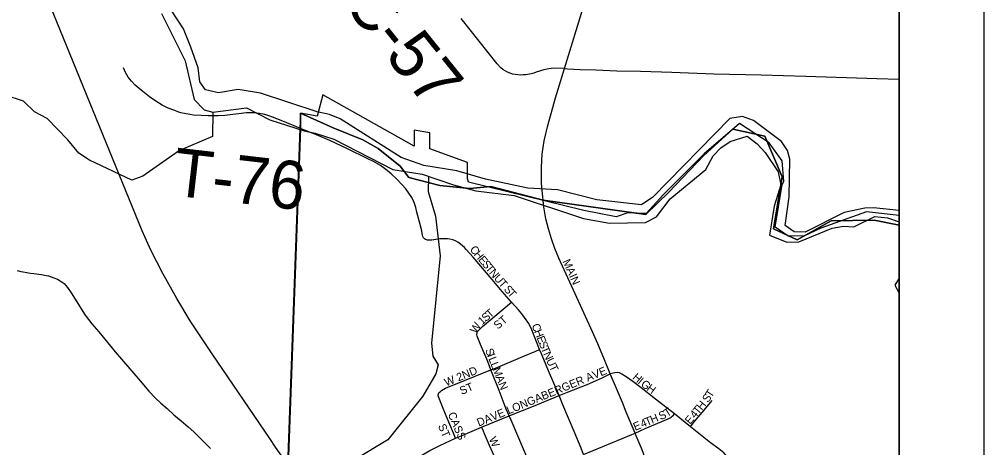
# Model space of a CAD drawing. Extents: x 0 to 34, y 0 to 22.
# Drawn here: x 29.776 to 30.917, y 15.366 to 15.873 of the extents above; entities that cross this region are included whole.
import ezdxf

# ---------------------------------------------------------------- set-up
doc = ezdxf.new("R2010")
doc.units = 0
for name, color, linetype in [('GM_X_Adjacent_County', 7, 'Continuous'), ('GM_X_City_Street', 7, 'Continuous'), ('GM_X_City_Street_Text', 7, 'Continuous'), ('GM_X_Corporation', 7, 'Continuous'), ('GM_X_County', 7, 'Continuous'), ('GM_X_County_Road', 7, 'Continuous'), ('GM_X_County_Road_Text', 7, 'Continuous'), ('GM_X_Minor_River', 7, 'Continuous'), ('GM_X_State_Route', 7, 'Continuous'), ('GM_X_Township', 7, 'Continuous'), ('GM_X_Township_Road', 7, 'Continuous'), ('GM_X_Township_Road_Text', 7, 'Continuous'), ('SH_Data', 7, 'Continuous')]:
    doc.layers.add(name, color=color, linetype=linetype)

msp = doc.modelspace()

# ---------------------------------------------------------------- linework, layer by layer
at = {"layer": 'GM_X_Adjacent_County'}
msp.add_lwpolyline([(24.0167, 18.0693), (24.0167, 14.1), (30.8167, 14.1), (30.8167, 17.8174)], dxfattribs=at)
at = {"layer": 'GM_X_City_Street'}
for points in [[(30.3579, 15.5381), (30.3471, 15.5507), (30.335, 15.5649), (30.3129, 15.5911), (30.3044, 15.6003), (30.3023, 15.6026), (30.3001, 15.6047), (30.2977, 15.6067), (30.2946, 15.6088), (30.2919, 15.6105), (30.2885, 15.6119), (30.2852, 15.6127), (30.2822, 15.6131), (30.2779, 15.6131), (30.2734, 15.6129), (30.2637, 15.6113), (30.2607, 15.6112), (30.2588, 15.6113), (30.2575, 15.6116), (30.2562, 15.6122), (30.2551, 15.6131), (30.2541, 15.6142), (30.2533, 15.6156), (30.2527, 15.6171), (30.2515, 15.624), (30.2462, 15.6445), (30.2447, 15.6501), (30.2428, 15.6559), (30.24, 15.6617), (30.2366, 15.667), (30.2332, 15.672), (30.2285, 15.6773), (30.2226, 15.6834), (30.2158, 15.6897), (30.2111, 15.6939), (30.2029, 15.6999), (30.195, 15.7045), (30.1881, 15.7077), (30.1641, 15.7196), (30.1431, 15.7293), (30.1301, 15.7347), (30.1084, 15.7436), (30.1038, 15.7455)], [(30.4749, 15.453), (30.4671, 15.4716), (30.46, 15.4888), (30.4539, 15.503), (30.4334, 15.548), (30.4141, 15.5901), (30.4095, 15.6015), (30.4053, 15.6131), (30.4018, 15.6249), (30.3988, 15.6368), (30.3971, 15.6459), (30.3963, 15.6508), (30.3959, 15.6542)], [(30.3172, 15.5003), (30.3173, 15.5016), (30.3175, 15.5023), (30.318, 15.5031), (30.3194, 15.5048), (30.3239, 15.509), (30.3579, 15.5381)], [(30.3912, 15.482), (30.3822, 15.5053), (30.3786, 15.5126), (30.3736, 15.5199), (30.3701, 15.5241), (30.3663, 15.529), (30.3579, 15.5381)], [(30.3338, 15.4578), (30.3299, 15.4678), (30.3212, 15.4878), (30.3181, 15.4956), (30.3174, 15.4979), (30.3172, 15.4992), (30.3172, 15.5003)], [(30.3338, 15.4578), (30.339, 15.4599), (30.3715, 15.4736), (30.3867, 15.48), (30.3912, 15.482)], [(30.4143, 15.4274), (30.402, 15.4566), (30.3936, 15.4767), (30.3912, 15.482)], [(30.2727, 15.4315), (30.274, 15.4324), (30.2752, 15.4333), (30.2801, 15.436), (30.3338, 15.4578)], [(30.3553, 15.4036), (30.3519, 15.4115), (30.3433, 15.4333), (30.3338, 15.4578)], [(30.4143, 15.4274), (30.4244, 15.4316), (30.4476, 15.4407), (30.4647, 15.4481), (30.4749, 15.453)], [(30.5509, 15.4059), (30.5283, 15.4233), (30.5113, 15.4366), (30.5015, 15.4442), (30.4939, 15.4495), (30.4887, 15.4528), (30.4858, 15.4543), (30.4832, 15.4548), (30.4802, 15.4544), (30.4749, 15.453)], [(30.5043, 15.3829), (30.5009, 15.3911), (30.4984, 15.3966), (30.4938, 15.4078), (30.4893, 15.4191), (30.4858, 15.4276), (30.4823, 15.4358), (30.4749, 15.453)], [(30.2919, 15.3768), (30.2893, 15.3829), (30.2808, 15.4036), (30.2755, 15.416), (30.2719, 15.4252), (30.2715, 15.4272), (30.2715, 15.4284), (30.2717, 15.4296), (30.2721, 15.4307), (30.2727, 15.4315)], [(30.3553, 15.4036), (30.3582, 15.4047), (30.3842, 15.415), (30.4143, 15.4274)], [(30.4433, 15.3578), (30.4404, 15.365), (30.4321, 15.3849), (30.4189, 15.4165), (30.4143, 15.4274)], [(30.5698, 15.3906), (30.5743, 15.3962), (30.5858, 15.41), (30.5935, 15.4191), (30.5954, 15.4214)], [(30.3227, 15.39), (30.3466, 15.4), (30.3553, 15.4036)], [(30.3856, 15.3339), (30.3835, 15.3384), (30.3736, 15.3612), (30.3576, 15.3983), (30.3553, 15.4036)], [(30.5043, 15.3829), (30.5162, 15.3883), (30.5435, 15.3998), (30.5457, 15.4011), (30.547, 15.402), (30.5482, 15.403), (30.5495, 15.4041), (30.5509, 15.4059)], [(30.5698, 15.3906), (30.5509, 15.4059)], [(30.6182, 15.3491), (30.6142, 15.3542), (30.6121, 15.3564), (30.6091, 15.3595), (30.6033, 15.3642), (30.5936, 15.3716), (30.5698, 15.3906)], [(30.2919, 15.3768), (30.3033, 15.3818), (30.3227, 15.39)], [(30.3227, 15.39), (30.3245, 15.3856), (30.3256, 15.3827), (30.3281, 15.3771), (30.3318, 15.3686), (30.3373, 15.3564), (30.3471, 15.3316), (30.3484, 15.3288), (30.3495, 15.3271), (30.3505, 15.3261), (30.3512, 15.3253), (30.3522, 15.3247), (30.3535, 15.324), (30.3541, 15.3238), (30.3549, 15.3236), (30.3562, 15.3235), (30.3578, 15.3236), (30.3598, 15.3238), (30.363, 15.3245), (30.3659, 15.3257), (30.3821, 15.3324)], [(30.4433, 15.3578), (30.5004, 15.3813), (30.5043, 15.3829)], [(30.533, 15.314), (30.5282, 15.3252), (30.5225, 15.3387), (30.5204, 15.3437), (30.5159, 15.3547), (30.5125, 15.363), (30.5102, 15.3687), (30.509, 15.3715), (30.5056, 15.3799), (30.5043, 15.3829)], [(30.177, 15.3087), (30.1998, 15.3237), (30.2321, 15.3442), (30.2474, 15.3541), (30.2616, 15.3623), (30.2733, 15.3683), (30.2919, 15.3768)]]:
    msp.add_lwpolyline(points, dxfattribs=at)
at = {"layer": 'GM_X_Corporation'}
msp.add_line((30.8167, 14.6286), (30.8167, 15.6406), dxfattribs=at)
msp.add_lwpolyline([(30.8167, 15.6406), (30.778, 15.6449), (30.7239, 15.6257), (30.7046, 15.6166), (30.6855, 15.6161), (30.6699, 15.6269), (30.6783, 15.6773), (30.6801, 15.681), (30.6781, 15.7053), (30.6627, 15.7266), (30.6278, 15.7494), (30.5858, 15.7134), (30.5377, 15.6653), (30.5175, 15.6428), (30.4957, 15.6437), (30.4819, 15.6389), (30.4435, 15.6466), (30.3072, 15.6799), (30.3059, 15.6843), (30.3059, 15.7033), (30.2614, 15.7195), (30.2614, 15.7384), (30.2428, 15.7417), (30.2428, 15.7227), (30.1349, 15.7832), (30.128, 15.758), (30.1084, 15.7615), (30.1076, 15.7433), (30.0929, 15.3447)], dxfattribs=at)
at = {"layer": 'GM_X_County'}
msp.add_lwpolyline([(24.0167, 18.0693), (24.0167, 14.1), (30.8167, 14.1), (30.8167, 17.8174)], dxfattribs=at)
at = {"layer": 'GM_X_County_Road'}
for points in [[(30.4208, 15.8144), (30.444, 15.8902), (30.4788, 16.0033), (30.4946, 16.0538), (30.5052, 16.0896), (30.5164, 16.1252), (30.5364, 16.1906), (30.5453, 16.2189), (30.5503, 16.2356)], [(30.4208, 15.8144), (30.4081, 15.8148), (30.4051, 15.8147), (30.4022, 15.8143), (30.3962, 15.8129), (30.3873, 15.8101), (30.3844, 15.8092), (30.3813, 15.8084), (30.3751, 15.8072), (30.3719, 15.8069), (30.3688, 15.8068), (30.3656, 15.807), (30.3624, 15.8074), (30.3593, 15.808), (30.3563, 15.8089), (30.3533, 15.8101), (30.3505, 15.8116), (30.3479, 15.8134), (30.3454, 15.8155), (30.3411, 15.8201), (30.3198, 15.8469), (30.2987, 15.8737)], [(30.3959, 15.6542), (30.3955, 15.6588), (30.3944, 15.6702), (30.3936, 15.679), (30.3936, 15.6977), (30.3945, 15.7133), (30.3967, 15.7288), (30.4009, 15.7471), (30.4103, 15.78), (30.4208, 15.8144)], [(30.4208, 15.8144), (30.4242, 15.8142), (30.4391, 15.8135), (30.4577, 15.8128), (30.4826, 15.8119), (30.5106, 15.8115), (30.5479, 15.8103), (30.5976, 15.8084), (30.6535, 15.8072), (30.7063, 15.8053), (30.7902, 15.8029), (30.8167, 15.8021)]]:
    msp.add_lwpolyline(points, dxfattribs=at)
at = {"layer": 'GM_X_Minor_River'}
for points in [[(30.8167, 15.6466), (30.7863, 15.6495), (30.7761, 15.6491), (30.7515, 15.6441), (30.7054, 15.6208), (30.6926, 15.6211), (30.6816, 15.6287), (30.6867, 15.6628), (30.6873, 15.7072), (30.6846, 15.7175), (30.6773, 15.7281), (30.6443, 15.753), (30.6314, 15.7579), (30.6163, 15.7552), (30.5254, 15.6623), (30.5119, 15.6531), (30.4592, 15.659), (30.4126, 15.671), (30.3774, 15.6728), (30.3274, 15.6836), (30.2933, 15.6935), (30.2544, 15.6999), (30.2277, 15.7091), (30.1552, 15.7551), (30.1427, 15.76), (30.1283, 15.7634), (30.0612, 15.7855), (30.0347, 15.7896), (30.0116, 15.7857), (29.9961, 15.7895), (29.9894, 15.7987), (29.9873, 15.8155), (29.9789, 15.8397), (29.97, 15.8615), (29.9391, 15.9088)], [(30.0049, 15.763), (30.0043, 15.7339), (29.9653, 15.7174), (29.9219, 15.6872), (29.909, 15.6823), (29.8589, 15.7059), (29.8463, 15.7142), (29.8334, 15.7301), (29.8086, 15.7554), (29.7938, 15.7633), (29.7808, 15.7758), (29.7592, 15.7829), (29.7349, 15.7862), (29.6985, 15.8012), (29.6312, 15.8484), (29.6213, 15.8548), (29.6099, 15.8627), (29.5427, 15.8874), (29.5317, 15.8889), (29.5143, 15.8824)], [(29.9442, 15.8796), (29.9721, 15.8235), (29.9825, 15.7777), (29.9943, 15.7656), (30.0049, 15.763), (30.0446, 15.768), (30.0723, 15.7537), (30.1129, 15.7409), (30.1257, 15.7379), (30.1477, 15.7308), (30.2175, 15.695), (30.2524, 15.6894), (30.2895, 15.677), (30.3157, 15.6699), (30.3611, 15.6644), (30.4434, 15.637), (30.4741, 15.6314), (30.5165, 15.6323), (30.5297, 15.6388), (30.5459, 15.6601), (30.5881, 15.6951), (30.5968, 15.7111), (30.6055, 15.7206), (30.6168, 15.7282), (30.6368, 15.7344), (30.6486, 15.7253), (30.6581, 15.7151), (30.6737, 15.6924), (30.6768, 15.6768), (30.6686, 15.6518), (30.6634, 15.6172), (30.6839, 15.609), (30.6979, 15.6094), (30.7372, 15.6254)], [(30.26, 15.6869), (30.2593, 15.669), (30.2682, 15.6398), (30.2737, 15.5928), (30.2635, 15.4895), (30.2651, 15.474), (30.2712, 15.4638), (30.2686, 15.4531), (30.2532, 15.4269), (30.2118, 15.3751), (30.1732, 15.3518), (30.124, 15.3353), (30.0676, 15.3214), (30.0237, 15.3053), (29.9904, 15.301), (29.9449, 15.2875), (29.917, 15.2688), (29.8675, 15.2253), (29.8482, 15.2138), (29.8112, 15.1936), (29.7757, 15.16)], [(30.7372, 15.6254), (30.7508, 15.6281), (30.763, 15.6271), (30.7879, 15.6393), (30.8027, 15.6378), (30.8167, 15.6329)], [(30.8167, 15.5662), (30.8117, 15.5582), (30.8167, 15.5487)]]:
    msp.add_lwpolyline(points, dxfattribs=at)
at = {"layer": 'GM_X_State_Route'}
msp.add_lwpolyline([(30.0929, 15.3462), (30.079, 15.3665), (30.0722, 15.3767), (30.0038, 15.4768), (29.9781, 15.5157), (29.962, 15.5422), (29.9454, 15.572), (29.9314, 15.5997), (29.9213, 15.6224), (29.8203, 15.8697), (29.8095, 15.8962)], dxfattribs=at)
at = {"layer": 'GM_X_Township'}
msp.add_line((30.8167, 15.629), (30.8167, 17.8174), dxfattribs=at)
for points in [[(30.8167, 15.629), (30.7871, 15.6349), (30.7362, 15.6342), (30.6958, 15.6119), (30.6678, 15.6247), (30.6782, 15.6864), (30.6578, 15.7345), (30.6199, 15.7428), (30.585, 15.7113), (30.544, 15.6681), (30.5169, 15.6418), (30.3955, 15.6588), (30.3337, 15.6747), (30.3087, 15.6727), (30.2731, 15.6761), (30.2367, 15.6857), (30.2263, 15.6991), (30.2004, 15.7198), (30.1822, 15.7301), (30.1471, 15.7445), (30.1084, 15.7615), (30.1084, 15.7436), (30.0937, 15.345)], [(30.0937, 15.345), (30.1084, 15.7436), (30.1084, 15.7615), (30.1471, 15.7445), (30.1822, 15.7301), (30.2004, 15.7198), (30.2263, 15.6991), (30.2367, 15.6857), (30.2731, 15.6761), (30.3087, 15.6727), (30.3337, 15.6747), (30.3955, 15.6588), (30.5169, 15.6418), (30.544, 15.6681), (30.585, 15.7113), (30.6199, 15.7428), (30.6578, 15.7345), (30.6782, 15.6864), (30.6678, 15.6247), (30.6958, 15.6119), (30.7362, 15.6342), (30.7871, 15.6349), (30.8167, 15.629)], [(30.0847, 14.1), (30.8167, 14.1), (30.8167, 15.629)]]:
    msp.add_lwpolyline(points, dxfattribs=at)
at = {"layer": 'GM_X_Township_Road'}
for points in [[(30.1038, 15.7455), (30.101, 15.7466), (30.0837, 15.7537), (30.0721, 15.7583), (30.0661, 15.76), (30.06, 15.7613), (30.0539, 15.762), (30.0475, 15.7622), (30.0444, 15.762), (30.0189, 15.759), (30.0112, 15.7586), (29.9991, 15.7584), (29.9908, 15.759), (29.982, 15.7595), (29.9731, 15.7609), (29.967, 15.7622), (29.9632, 15.7633), (29.9596, 15.7647), (29.9521, 15.7677), (29.945, 15.7712), (29.9374, 15.7757), (29.9298, 15.7811), (29.9199, 15.7889), (29.9129, 15.795), (29.9086, 15.7995), (29.9047, 15.8044), (29.9029, 15.8069), (29.9014, 15.8097), (29.9001, 15.8125), (29.899, 15.8154)], [(29.7731, 15.5754), (29.7775, 15.5744), (29.7802, 15.5738), (29.7848, 15.5729), (29.7888, 15.5724), (29.7929, 15.5721), (29.8019, 15.5708), (29.8076, 15.5697), (29.8102, 15.569), (29.8168, 15.5668), (29.8208, 15.5652), (29.8243, 15.5632), (29.8288, 15.5599), (29.8328, 15.5552), (29.8371, 15.5491), (29.8539, 15.5227), (29.8616, 15.5124), (29.8697, 15.5027), (29.8894, 15.4793), (29.9187, 15.445), (29.9291, 15.4328), (29.9371, 15.4242), (29.9434, 15.4184), (29.9509, 15.412), (29.9588, 15.4045), (29.9673, 15.3974), (29.9755, 15.3905), (29.9822, 15.3843), (30.0019, 15.3646)]]:
    msp.add_lwpolyline(points, dxfattribs=at)
at = {"layer": 'SH_Data'}
for points in [[(23.9167, 21), (30.9167, 21), (30.9167, 14), (23.9167, 14)], [(24.0167, 20.9), (30.8167, 20.9), (30.8167, 14.1), (24.0167, 14.1)]]:
    msp.add_lwpolyline(points, close=True, dxfattribs=at)

# ---------------------------------------------------------------- texts
at = {"layer": 'GM_X_City_Street_Text'}
for s, rotation, p in [('C', 309.6874, (30.3081, 15.6001)), ('H', 309.6769, (30.3129, 15.5943)), ('E', 309.6796, (30.3182, 15.5879)), ('S', 309.6796, (30.3225, 15.5828)), ('MAIN', 293.8048, (30.4183, 15.5864)), ('T', 309.6796, (30.3267, 15.5777)), ('N', 309.998, (30.331, 15.5725)), ('U', 311.6074, (30.3366, 15.5659)), ('T', 311.9845, (30.3421, 15.5596)), ('S', 311.9845, (30.3483, 15.5528)), ('T', 311.9852, (30.3527, 15.5478)), ('T', 40.8235, (30.3327, 15.5187)), ('1', 41.3093, (30.3233, 15.5105)), ('S', 40.9777, (30.3277, 15.5143)), ('ST', 39.8074, (30.3418, 15.5053)), ('W', 57.681, (30.3162, 15.5001)), ('C', 291.824, (30.3817, 15.5105)), ('H', 291.8157, (30.3845, 15.5035)), ('E', 291.8349, (30.3876, 15.4958)), ('S', 291.218, (30.3267, 15.4813)), ('S', 291.8319, (30.3901, 15.4896)), ('T', 292.4285, (30.3926, 15.4833)), ('I', 291.2007, (30.3291, 15.4751)), ('L', 291.2091, (30.3306, 15.4712)), ('N', 294.5458, (30.3953, 15.4768)), ('U', 295.014, (30.3988, 15.4691)), ('W 2ND', 22.5183, (30.281, 15.4381)), ('DAVE LONGABERGER AVE', 22.3967, (30.3194, 15.3906)), ('L', 291.1925, (30.333, 15.465)), ('M', 291.2205, (30.3355, 15.4587)), ('T', 295.0252, (30.4023, 15.4616)), ('A', 291.2007, (30.3391, 15.4494)), ('H', 319.4864, (30.5004, 15.4478)), ('I', 319.7271, (30.5067, 15.4424)), ('ST', 23.2005, (30.2991, 15.4281)), ('N', 292.6524, (30.3422, 15.4414)), ('G', 322.2807, (30.5103, 15.4394)), ('H', 323.702, (30.5171, 15.4342)), ('S', 54.6515, (30.5905, 15.4184)), ('T', 57.1633, (30.5946, 15.4242)), ('T', 33.4961, (30.5422, 15.4017)), ('T', 50.7471, (30.579, 15.4042)), ('H', 50.7833, (30.5832, 15.4094)), ('CASS', 292.9904, (30.2825, 15.4055)), ('T', 22.7293, (30.5182, 15.3914)), ('H', 22.753, (30.5244, 15.394)), ('S', 22.725, (30.5344, 15.3982)), ('E', 50.7471, (30.5695, 15.3926)), ('4', 50.7501, (30.5753, 15.3997)), ('ST', 293.2005, (30.2709, 15.3916)), ('E', 22.7502, (30.5044, 15.3856)), ('4', 22.7158, (30.5128, 15.3892)), ('W', 294.5873, (30.3309, 15.3761))]:
    msp.add_text(s, height=0.00947, rotation=rotation, dxfattribs=at).set_placement(p)
at = {"layer": 'GM_X_County_Road_Text'}
msp.add_text('C-57', height=0.05682, rotation=308.7654, dxfattribs=at).set_placement((30.157, 15.8925))
at = {"layer": 'GM_X_Township_Road_Text'}
msp.add_text('T-76', height=0.05682, rotation=353.385, dxfattribs=at).set_placement((29.9555, 15.6645))

doc.saveas('drawing.dxf')
